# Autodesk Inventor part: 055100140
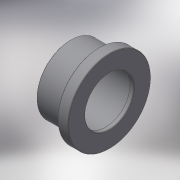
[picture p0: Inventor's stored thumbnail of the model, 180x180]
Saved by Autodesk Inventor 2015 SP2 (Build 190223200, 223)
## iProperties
Created: 2017-10
Part Number: 055100140
Material: Generic
Description: PLASSON FLANGE FLAT AD.-CEM 140
Document SubType Name: Modeling
Designer: KIM
Mass: 548.011 g
Surface Area: 1077.94 cm^2
Volume: 548.011 cm^3
Density: 1 g/cm^3
Appearance: Default
Author: KIM
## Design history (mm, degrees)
derived "055100.ipt"
feature "Solid1::055100.ipt"
tag "TaggingFeature1"
body "Solid1"
other parameters: "d0" = 82, "d1" = 163, "d3" = 126, "d4" = 12, "d5" = 76, "d6" = 188, "d8" = 1.4, "E_" = 163, "E_1" = 188, "l_" = 76, "B_" = 12, "H_" = 82
